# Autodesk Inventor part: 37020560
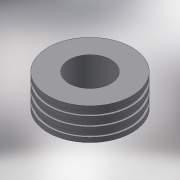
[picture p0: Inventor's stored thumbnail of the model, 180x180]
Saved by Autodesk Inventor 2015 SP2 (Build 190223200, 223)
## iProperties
Created: 2017-08
Part Number: 37020560
Material: Generic
Description: PLASSON MAN HOLE ADAPTOR 560
Document SubType Name: Modeling
Designer: Кирилл
Density: 1 g/cm^3
Appearance: Default
Author: Кирилл
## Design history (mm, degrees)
derived "37020-477207.ipt"
feature "Solid1::37020-477207.ipt"
tag "TaggingFeature1"
body "Solid1"
other parameters: "d0" = 135, "d1" = 705, "d2" = 669.75, "d3" = 494, "d6" = 51, "L_" = 135, "d_1" = 494, "D_" = 705, "H_" = 51
